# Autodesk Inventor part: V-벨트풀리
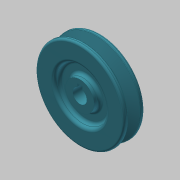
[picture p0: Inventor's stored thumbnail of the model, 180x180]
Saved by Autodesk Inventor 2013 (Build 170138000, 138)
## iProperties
Created: 2019-09
Part Number: V-벨트풀리
Material: 알루미늄 6061
Document SubType Name: Modeling
Designer: mduedu
Density: 2.71 g/cm^3
Mass: 202.902 g
Surface Area: 230.066 cm^2
Volume: 74.8717 cm^3
Author: mduedu
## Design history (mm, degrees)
sketch "스케치1"
  geometry: L1 (-10, 0)-(10, 0); L2 (10, 0)-(10, 43.5); L3 (10, 43.5)-(-10, 43.5); L4 (-10, 43.5)-(-10, 0); L5 (0, 0)-(0, 43.5); L6 (-5.976, 43.5)-(-2.154, 31); L7 (-2.154, 31)-(2.154, 31); L8 (2.154, 31)-(5.976, 43.5); L9 (-10, 39)-(10, 39); 3 further points
  constraints: 18 end point, 8 point on line, 3 perpendicular, 2 midpoint, 2 parallel, 1 coincident, 1 horizontal, 1 other
  dimensions: "d0" = 87 diameter of L3 L1; "d3" = 12.5 distance between parallel lines of L7 L3; "d4" = 34 deg angle of L8 L6; "d5" = 20 distance between parallel lines of L2 L4; "d6" = 8 distance between parallel lines of L9 L7; "d7" = 9.2 distance of point (4.6, 39) point (-4.6, 39)
revolve "회전1" sketch "스케치1" stored, may be unused: angle "d8" = 90 deg
sketch "스케치2"
  geometry: C1 r 14 at (0, 0); C2 r 25 at (0, 0); 1 further point
  constraints: 2 centre point, 2 coincident
  dimensions: "d9" = 28 diameter of C1; "d10" = 50 diameter of C2
extrude "돌출1" cut sketch "스케치2" distance "d11" = 6; taper "d12" = 0 deg
fillet "모깎기1" dims "d13" = 3
fillet "모깎기2" dims "d14" = 3
fillet "모깎기3" dims "d15" = 0.5, "d16" = 1, "d17" = 2
sketch "스케치3"
  geometry: L1 (-2.5, 6.538)-(2.5, 6.538); L2 (2.5, 6.538)-(2.5, 9.3); L3 (2.5, 9.3)-(-2.5, 9.3); L4 (-2.5, 9.3)-(-2.5, 6.538); A1 r 7 centre (0, 0) between (-2.5, 6.538) and (2.5, 6.538); 1 further point
  constraints: 8 end point, 2 parallel, 2 point on circle, 1 centre point, 1 coincident, 1 horizontal, 1 perpendicular
  dimensions: "d18" = 14 diameter of A1; "d20" = 5 distance of L2.end L3.end; "d21" = 16.3 dimension on A1 L3
extrude "돌출2" cut sketch "스케치3" stored distance "d22" = 6; taper "d23" = 0 deg
node "솔리드1"
mirror "대칭1"
